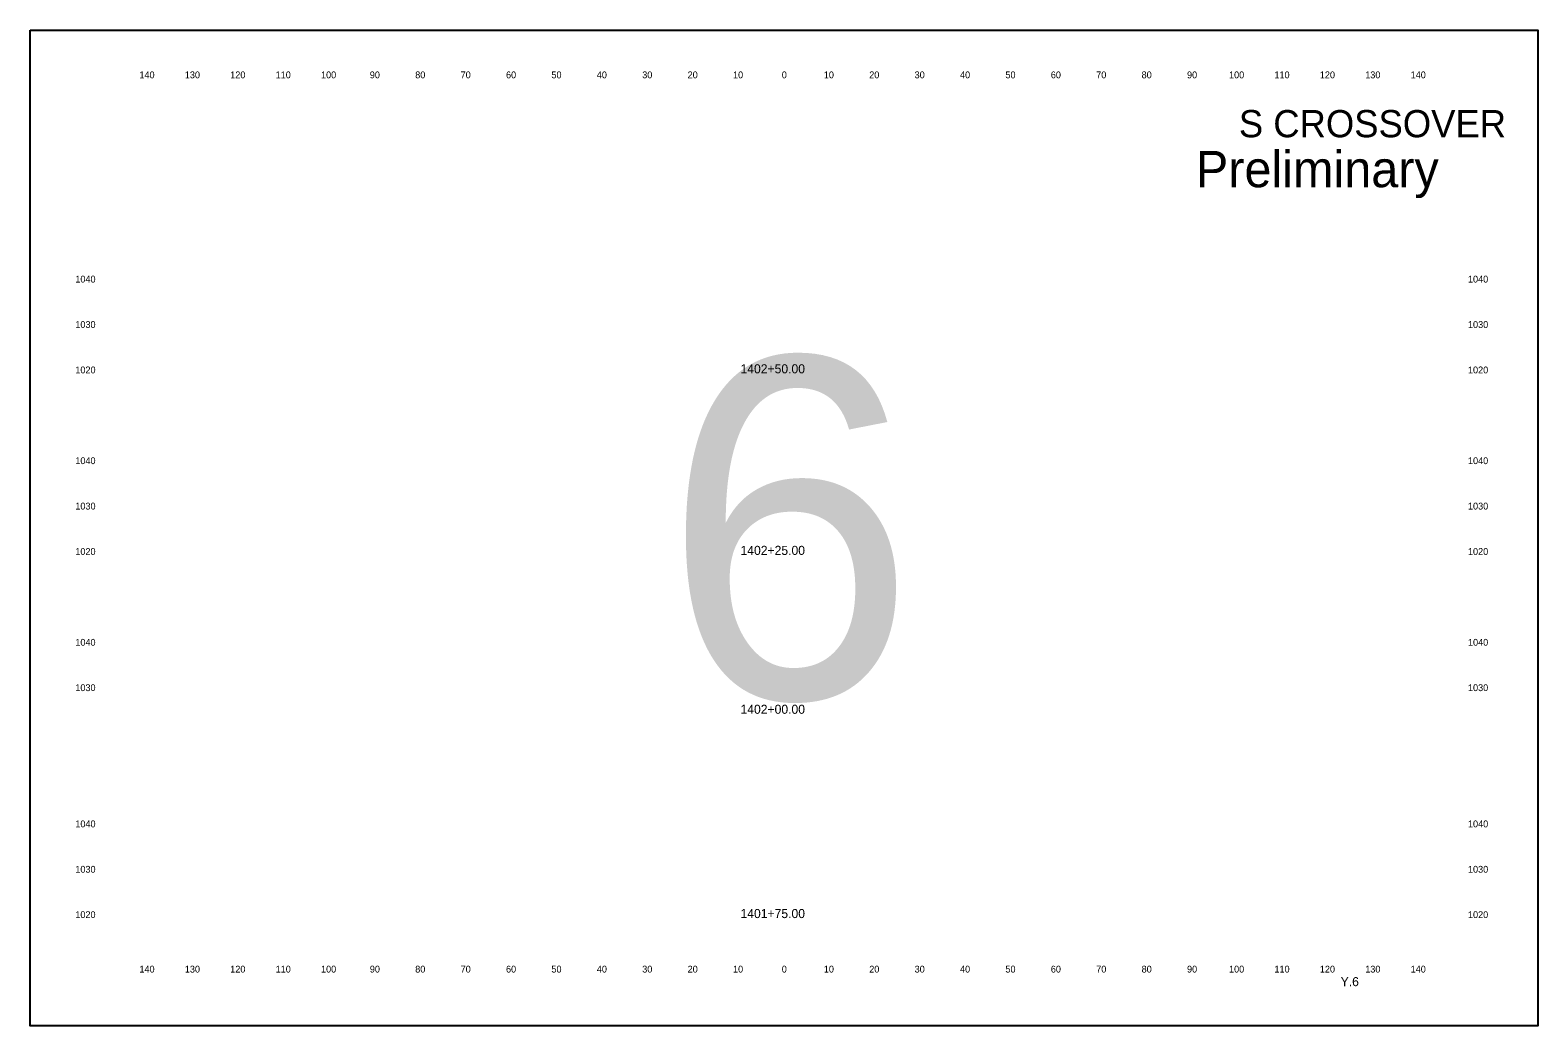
# Model space of a CAD drawing. Extents: x 10123 to 14768, y 9730 to 9950.
# Drawn here: x 11923.2 to 12255.3, y 9730.3 to 9949.6 of the extents above; entities that cross this region are included whole.
import ezdxf

# ---------------------------------------------------------------- set-up
doc = ezdxf.new("R2010")
doc.units = 0
for name, color, linetype in [('dsnTextCpn', 7, 'Continuous'), ('dsnTextCpnTitleSheetLocDesc', 7, 'Continuous'), ('dsnTextCpnTitleSheetPIN', 7, 'Continuous'), ('dsnTextCpnTitleSheetWorkType', 7, 'Continuous')]:
    doc.layers.add(name, color=color, linetype=linetype)

msp = doc.modelspace()

# ---------------------------------------------------------------- linework, layer by layer
at = {"layer": 'dsnTextCpnTitleSheetWorkType'}
msp.add_lwpolyline([(11923.21, 9949.6), (12255.29, 9949.6), (12255.29, 9730.26), (11923.21, 9730.26)], close=True, dxfattribs=at)

# ---------------------------------------------------------------- texts
at = {"layer": 'dsnTextCpn'}
for s, height, p in [('140', 1.5, (11947.27, 9939)), ('130', 1.5, (11957.27, 9939)), ('120', 1.5, (11967.27, 9939)), ('110', 1.5, (11977.27, 9939)), ('100', 1.5, (11987.27, 9939)), ('90', 1.5, (11998.02, 9939)), ('80', 1.5, (12008.02, 9939)), ('70', 1.5, (12018.02, 9939)), ('60', 1.5, (12028.02, 9939)), ('50', 1.5, (12038.02, 9939)), ('40', 1.5, (12048.02, 9939)), ('30', 1.5, (12058.02, 9939)), ('20', 1.5, (12068.02, 9939)), ('10', 1.5, (12078.02, 9939)), ('0', 1.5, (12088.76, 9939)), ('0', 1.5, (12088.76, 9939)), ('10', 1.5, (12098.02, 9939)), ('20', 1.5, (12108.02, 9939)), ('30', 1.5, (12118.02, 9939)), ('40', 1.5, (12128.02, 9939)), ('50', 1.5, (12138.02, 9939)), ('60', 1.5, (12148.02, 9939)), ('70', 1.5, (12158.02, 9939)), ('80', 1.5, (12168.02, 9939)), ('90', 1.5, (12178.02, 9939)), ('100', 1.5, (12187.27, 9939)), ('110', 1.5, (12197.27, 9939)), ('120', 1.5, (12207.27, 9939)), ('130', 1.5, (12217.27, 9939)), ('140', 1.5, (12227.27, 9939)), ('S CROSSOVER', 6, (12189.44, 9926)), ('1040', 1.5, (11933.15, 9894)), ('1040', 1.5, (12239.9, 9894)), ('1030', 1.5, (11933.15, 9884)), ('1030', 1.5, (12239.9, 9884)), ('1020', 1.5, (11933.15, 9874)), ('1402+50.00', 2, (12079.67, 9874)), ('1020', 1.5, (12239.9, 9874)), ('1040', 1.5, (11933.15, 9854)), ('1040', 1.5, (12239.9, 9854)), ('1030', 1.5, (11933.15, 9844)), ('1030', 1.5, (12239.9, 9844)), ('1020', 1.5, (11933.15, 9834)), ('1402+25.00', 2, (12079.67, 9834)), ('1020', 1.5, (12239.9, 9834)), ('1040', 1.5, (11933.15, 9814)), ('1040', 1.5, (12239.9, 9814)), ('1030', 1.5, (11933.15, 9804)), ('1030', 1.5, (12239.9, 9804)), ('1402+00.00', 2, (12079.67, 9799)), ('1040', 1.5, (11933.15, 9774)), ('1040', 1.5, (12239.9, 9774)), ('1030', 1.5, (11933.15, 9764)), ('1030', 1.5, (12239.9, 9764)), ('1020', 1.5, (11933.15, 9754)), ('1401+75.00', 2, (12079.67, 9754)), ('1020', 1.5, (12239.9, 9754)), ('140', 1.5, (11947.27, 9742)), ('130', 1.5, (11957.27, 9742)), ('120', 1.5, (11967.27, 9742)), ('110', 1.5, (11977.27, 9742)), ('100', 1.5, (11987.27, 9742)), ('90', 1.5, (11998.02, 9742)), ('80', 1.5, (12008.02, 9742)), ('70', 1.5, (12018.02, 9742)), ('60', 1.5, (12028.02, 9742)), ('50', 1.5, (12038.02, 9742)), ('40', 1.5, (12048.02, 9742)), ('30', 1.5, (12058.02, 9742)), ('20', 1.5, (12068.02, 9742)), ('10', 1.5, (12078.02, 9742)), ('0', 1.5, (12088.76, 9742)), ('0', 1.5, (12088.76, 9742)), ('10', 1.5, (12098.02, 9742)), ('20', 1.5, (12108.02, 9742)), ('30', 1.5, (12118.02, 9742)), ('40', 1.5, (12128.02, 9742)), ('50', 1.5, (12138.02, 9742)), ('60', 1.5, (12148.02, 9742)), ('70', 1.5, (12158.02, 9742)), ('80', 1.5, (12168.02, 9742)), ('90', 1.5, (12178.02, 9742)), ('100', 1.5, (12187.27, 9742)), ('110', 1.5, (12197.27, 9742)), ('120', 1.5, (12207.27, 9742)), ('130', 1.5, (12217.27, 9742)), ('140', 1.5, (12227.27, 9742))]:
    msp.add_text(s, height=height, dxfattribs=at).set_placement(p)
at = {"layer": 'dsnTextCpnTitleSheetLocDesc'}
msp.add_text('Preliminary', height=8, dxfattribs=at).set_placement((12179.97, 9915))
at = {"layer": 'dsnTextCpnTitleSheetPIN'}
msp.add_text('Y.6', height=2, dxfattribs=at).set_placement((12211.86, 9739))
at = {"layer": 'dsnTextCpnTitleSheetWorkType'}
msp.add_text('6', height=75, dxfattribs=at).set_placement((12062.55, 9802.43))

doc.saveas('drawing.dxf')
